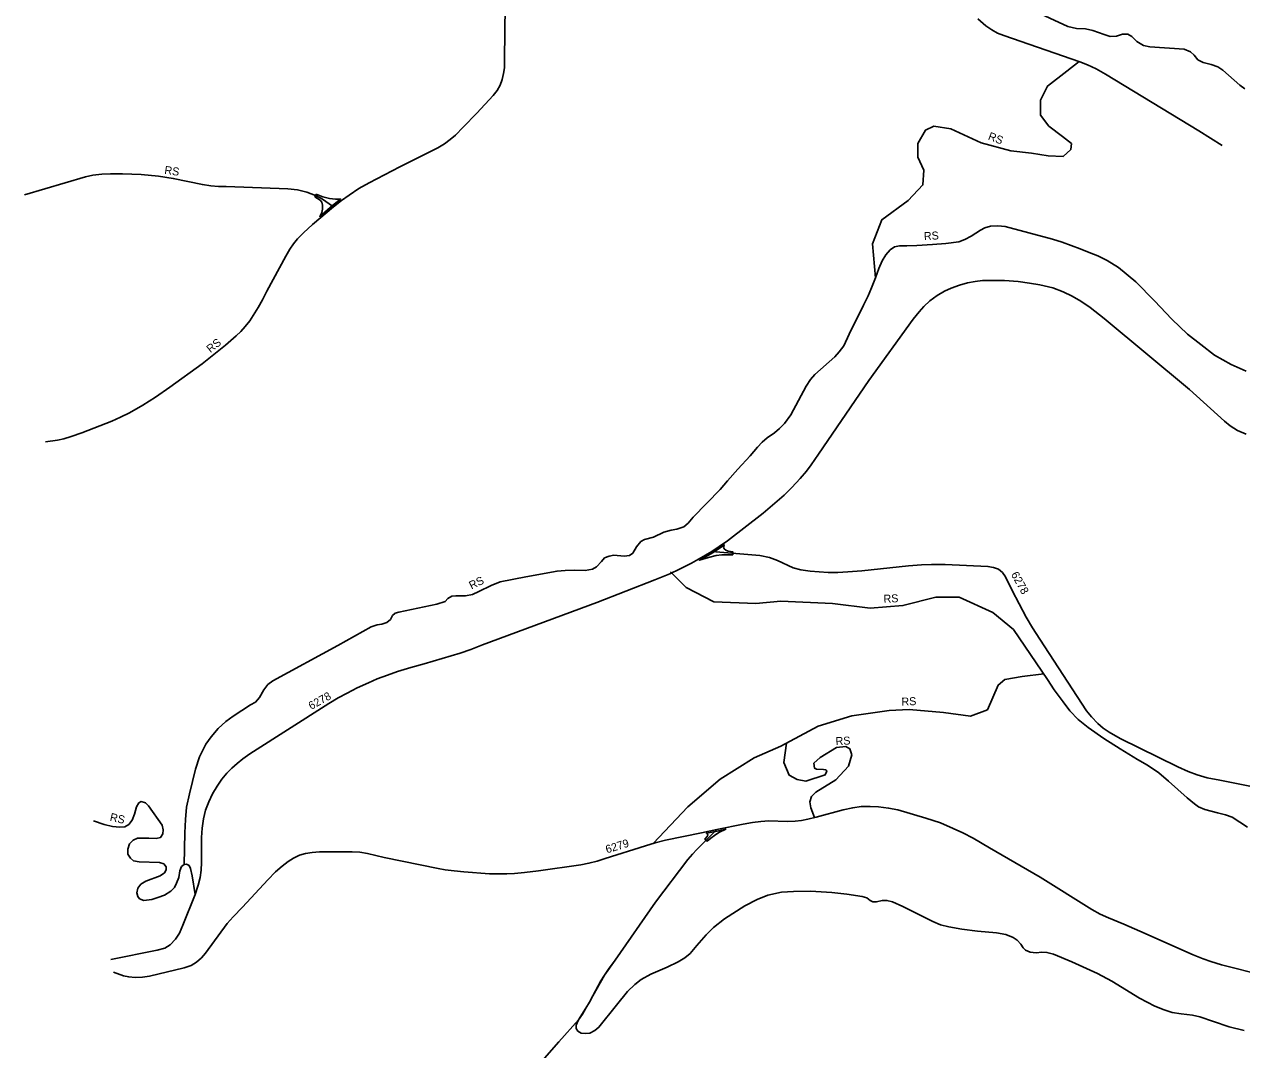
# Model space of a CAD drawing. Extents: x -546703 to -534152, y -1046534 to -1035676.
# Drawn here: x -546703 to -545182, y -1045782 to -1044501 of the extents above; entities that cross this region are included whole.
import ezdxf

# ---------------------------------------------------------------- set-up
doc = ezdxf.new("R2010")
doc.units = 0
doc.layers.add('Vrstva 11', color=7, linetype='Continuous')
doc.layers.add('Vrstva 22', color=7, linetype='Continuous')

msp = doc.modelspace()

# ---------------------------------------------------------------- linework, layer by layer
at = {"layer": 'Vrstva 11'}
for points in [[(-546676, -1045022.9), (-546661.2, -1045020.6), (-546653.1, -1045018.9), (-546644.2, -1045016.2), (-546630.9, -1045011.5), (-546593.5, -1044996.9), (-546582.7, -1044992), (-546571.2, -1044986.4), (-546554.5, -1044976.9), (-546538.8, -1044967), (-546521, -1044954.6), (-546480.4, -1044925.5), (-546451.3, -1044902.2), (-546437.8, -1044890.2), (-546432.3, -1044884.8), (-546426.6, -1044878.6), (-546421.1, -1044871.5), (-546416.6, -1044864.9), (-546410.4, -1044855), (-546405, -1044845.6), (-546399.5, -1044834.8), (-546376.1, -1044790.9), (-546371.1, -1044782.3), (-546366.5, -1044775.5), (-546361.4, -1044769.4), (-546353.7, -1044761.7), (-546342.4, -1044751.4), (-546316.5, -1044729.3), (-546306.3, -1044721.2), (-546296.8, -1044714.7), (-546284.5, -1044706.6), (-546271.9, -1044699.2), (-546233.4, -1044679.4), (-546185.9, -1044655.7), (-546177.7, -1044650.8), (-546170.5, -1044645.4), (-546163.9, -1044639.6), (-546154.4, -1044629.8), (-546137.3, -1044612.3), (-546116.7, -1044590.1), (-546111.8, -1044584.1), (-546108.3, -1044577.3), (-546105.8, -1044570.4), (-546103.8, -1044562.7), (-546102.9, -1044555.6), (-546102.5, -1044544.8), (-546102, -1044477.9)], [(-545511.3, -1044494.4), (-545501.1, -1044503.4), (-545493.9, -1044508.4), (-545486.9, -1044512.3), (-545478.9, -1044515.5), (-545383.7, -1044548.1), (-545374.1, -1044552), (-545363.5, -1044557), (-545351.7, -1044563.6), (-545235.3, -1044634.5), (-545206.2, -1044652.5)], [(-546702.6, -1044714.5), (-546626.2, -1044691.8), (-546617.2, -1044689.9), (-546605.7, -1044688.3), (-546594.8, -1044687.9), (-546580.2, -1044687.9), (-546556.6, -1044689.1), (-546535.1, -1044691), (-546516.5, -1044693.7), (-546480.1, -1044701.5), (-546469.8, -1044703), (-546460.1, -1044703.7), (-546450.5, -1044703.8), (-546373.6, -1044706.7), (-546361.4, -1044708.2), (-546349.8, -1044711), (-546338.8, -1044715), (-546331.4, -1044719), (-546316.5, -1044729.3)], [(-546594.6, -1045669.3), (-546536.5, -1045657.6), (-546527.2, -1045655), (-546520.4, -1045650.8), (-546513.9, -1045643.9), (-546508.9, -1045636.2), (-546504.6, -1045626.5), (-546489.1, -1045588.2), (-546485.5, -1045576.6), (-546483, -1045566.7), (-546481.8, -1045557.7), (-546481.2, -1045548), (-546481.2, -1045516.9), (-546480.4, -1045505.3), (-546478.6, -1045493.4), (-546476.2, -1045482.7), (-546472.3, -1045472.2), (-546467.5, -1045462.3), (-546461.8, -1045452.8), (-546455.8, -1045444), (-546449.7, -1045436.7), (-546443.5, -1045430.4), (-546436.8, -1045424.4), (-546429.7, -1045418.7), (-546420.9, -1045412.6), (-546322.2, -1045349.4), (-546310.5, -1045342.4), (-546299.4, -1045336.5), (-546286.8, -1045330), (-546272.5, -1045323.6), (-546261.8, -1045318.9), (-546248.7, -1045314.1), (-546236.4, -1045309.8), (-546219.8, -1045304.8), (-546202.9, -1045300), (-546158.1, -1045286.6), (-546144.9, -1045282), (-546130.2, -1045276.3), (-545987.5, -1045223.6), (-545915, -1045195.3), (-545896.3, -1045187.7), (-545884.2, -1045181.8), (-545869.2, -1045174.3), (-545851.7, -1045164.4), (-545843.6, -1045159.8), (-545834.3, -1045153.7), (-545824.2, -1045146.3), (-545779.4, -1045111.7), (-545767.7, -1045101.8), (-545753.2, -1045089.5), (-545743.7, -1045079.8), (-545733.4, -1045068.7), (-545725.5, -1045059.4), (-545719.5, -1045051.5), (-545710.2, -1045038), (-545647.6, -1044946.3), (-545591.9, -1044869.6), (-545584.4, -1044860.3), (-545578.7, -1044853.7), (-545571.1, -1044846.6), (-545562.1, -1044840), (-545552.8, -1044834.6), (-545544.6, -1044830.9), (-545534, -1044827), (-545524.4, -1044824.3), (-545514.8, -1044822.6), (-545505.4, -1044821.5), (-545495.2, -1044821.2), (-545478.1, -1044821.5), (-545460.9, -1044822.7), (-545446.9, -1044824.5), (-545434, -1044826.5), (-545417.6, -1044830.5), (-545404.6, -1044835.3), (-545393.3, -1044840.9), (-545382.4, -1044847.1), (-545371, -1044855), (-545353.6, -1044868.8), (-545246.9, -1044957.6), (-545203.1, -1044997), (-545195.8, -1045002.7), (-545186.7, -1045008.5), (-545176.2, -1045013)], [(-545843.6, -1045159.8), (-545783.8, -1045164.8), (-545771.6, -1045167.3), (-545761.6, -1045171), (-545742.1, -1045180), (-545732.6, -1045182.5), (-545720.6, -1045184.5), (-545698.3, -1045186.1), (-545686.2, -1045186), (-545673.9, -1045185.3), (-545656.1, -1045184), (-545598, -1045177.8), (-545581.5, -1045176.5), (-545569, -1045175.8), (-545552.3, -1045176.1), (-545498.6, -1045178.3), (-545491.6, -1045179.6), (-545485.3, -1045182), (-545480.4, -1045186), (-545476.9, -1045191.5), (-545468.4, -1045208.3), (-545450.9, -1045241.7), (-545443.1, -1045255.1), (-545433.9, -1045269.1), (-545375.4, -1045358.7), (-545369.4, -1045366.4), (-545361.5, -1045374.4), (-545354.7, -1045380.2), (-545347.2, -1045385.2), (-545333.5, -1045393.1), (-545261.4, -1045428.5), (-545248.3, -1045434.5), (-545237.3, -1045438.7), (-545224.7, -1045442.3), (-545208.9, -1045445.5), (-545136.2, -1045459.8)], [(-546591.2, -1045685), (-546578.9, -1045689.6), (-546572.1, -1045691.1), (-546564.3, -1045691.8), (-546555.1, -1045691.2), (-546546.1, -1045690), (-546503.1, -1045679.7), (-546494.3, -1045676.7), (-546487.4, -1045672.5), (-546481.2, -1045667), (-546476.2, -1045661.4), (-546449.1, -1045624.4), (-546441.8, -1045615.9), (-546430.2, -1045603.9), (-546398.3, -1045569.7), (-546388.7, -1045559.9), (-546380.6, -1045552.8), (-546373.2, -1045546.9), (-546366.3, -1045542.6), (-546358.9, -1045539), (-546351.2, -1045536.7), (-546343.1, -1045535.5), (-546333.7, -1045534.9), (-546292.9, -1045534.7), (-546283.5, -1045535.4), (-546273.7, -1045537.1), (-546252.9, -1045541.9), (-546185.7, -1045555.6), (-546177, -1045557.2), (-546165.6, -1045558.7), (-546153.7, -1045559.9), (-546121.4, -1045562.2), (-546109.7, -1045562.5), (-546099.8, -1045562.4), (-546090.1, -1045561.8), (-546077.8, -1045560.5), (-546060.1, -1045558.6), (-546007.5, -1045551.1), (-545997.3, -1045549.1), (-545987.1, -1045546.4), (-545977, -1045543.3), (-545926.5, -1045527.3), (-545914.5, -1045523.5), (-545901.5, -1045520.2), (-545856.7, -1045511.1), (-545837.4, -1045507.1), (-545804.7, -1045500.3), (-545793, -1045498.2), (-545782.5, -1045496.9), (-545772.6, -1045496.3), (-545749.4, -1045496.9), (-545739.6, -1045496.4), (-545731.6, -1045495.6), (-545723.7, -1045494.1), (-545713.3, -1045491.5), (-545679.7, -1045482.4), (-545667.6, -1045479.7), (-545657, -1045478.4), (-545646, -1045478.1), (-545635.2, -1045478.7), (-545622.8, -1045480.1), (-545611.4, -1045482.4), (-545576.1, -1045492.6), (-545558.1, -1045498.8), (-545542.1, -1045505.7), (-545530.2, -1045511), (-545517.2, -1045517.8), (-545496.8, -1045529.8), (-545433.6, -1045566.4), (-545368.9, -1045606.8), (-545358.3, -1045612.5), (-545348.1, -1045617.3), (-545328.8, -1045625.2), (-545309, -1045633.7), (-545242.2, -1045663.3), (-545229.7, -1045668.3), (-545220, -1045671.9), (-545206.8, -1045676), (-545101, -1045702.4)], [(-546070.6, -1045813), (-546034.9, -1045772.2), (-546010.4, -1045744.6), (-546005.4, -1045737.6), (-546000.9, -1045730.1), (-545996.5, -1045722.5), (-545992.4, -1045714.7), (-545982.2, -1045696.1), (-545977.7, -1045688.8), (-545972.1, -1045680.3), (-545964.4, -1045670), (-545914, -1045597.8), (-545873.6, -1045544.4), (-545867.9, -1045537.7), (-545862.5, -1045531.7), (-545837.4, -1045507.1)]]:
    msp.add_lwpolyline(points, dxfattribs=at)
for points in [[(-546338.1, -1044713.4), (-546329.6, -1044716.8), (-546321.3, -1044718.7), (-546314, -1044719.7), (-546307.5, -1044719.6), (-546317.8, -1044727.7), (-546333.5, -1044741.2), (-546331, -1044736.4), (-546330, -1044732.1), (-546330.1, -1044727.3), (-546331, -1044723.6), (-546333, -1044720.8), (-546339.5, -1044716.6)], [(-545833.3, -1045155.2), (-545842.7, -1045161.3), (-545850.8, -1045166), (-545859.1, -1045170.6), (-545847.8, -1045167.2), (-545838.3, -1045164.7), (-545831.1, -1045163.8), (-545817.5, -1045163.7), (-545817.4, -1045160.2), (-545823.4, -1045159.3), (-545826.3, -1045158.1), (-545828.3, -1045156.4), (-545828.9, -1045154.3), (-545828.1, -1045151.3)], [(-545837, -1045508.8), (-545826.3, -1045506.6), (-545834.7, -1045510.6), (-545840.5, -1045514.4), (-545844.8, -1045517.6), (-545849.5, -1045521.4), (-545852.2, -1045519.1), (-545849.4, -1045515.8), (-545848.7, -1045514), (-545849, -1045512.7), (-545850.5, -1045511.6)]]:
    msp.add_lwpolyline(points, close=True, dxfattribs=at)
at = {"layer": 'Vrstva 22'}
for points in [[(-545177.7, -1044581.8), (-545183.8, -1044577.3), (-545205.3, -1044558.7), (-545211.4, -1044554.5), (-545219.7, -1044551.7), (-545229.6, -1044549.1), (-545236.3, -1044545.6), (-545241.1, -1044539.8), (-545245.6, -1044535.6), (-545253.3, -1044532.4), (-545296.2, -1044529.5), (-545304.2, -1044527.6), (-545312.6, -1044522.8), (-545318.7, -1044516.7), (-545323.8, -1044513.8), (-545330.5, -1044513.5), (-545338.2, -1044516.1), (-545345.9, -1044516.4), (-545353.6, -1044514.2), (-545367.7, -1044509), (-545376.9, -1044507.1), (-545388.2, -1044506.5), (-545398.7, -1044504.2), (-545471.7, -1044469.9)], [(-545639.3, -1044818.1), (-545642.7, -1044775.3), (-545631.4, -1044745.5), (-545598.3, -1044721.3), (-545579.8, -1044701.9), (-545578.9, -1044683.4), (-545586.2, -1044667.2), (-545586.2, -1044650.3), (-545576.5, -1044633.4), (-545566.1, -1044628.5), (-545545.1, -1044631.7), (-545507.2, -1044649.5), (-545470.1, -1044659.2), (-545444.2, -1044662.4), (-545423.3, -1044665.6), (-545404.7, -1044666.4), (-545395, -1044657.6), (-545394.2, -1044650.3), (-545405.5, -1044641.4), (-545422.4, -1044628.5), (-545432.9, -1044614.8), (-545432.9, -1044596.2), (-545424.1, -1044578.5), (-545399.9, -1044560), (-545384.5, -1044547.8)], [(-546702.6, -1044714.5), (-546626.2, -1044691.8), (-546617.2, -1044689.9), (-546605.7, -1044688.3), (-546594.8, -1044687.9), (-546580.2, -1044687.9), (-546556.6, -1044689.1), (-546535.1, -1044691), (-546516.5, -1044693.7), (-546480.1, -1044701.5), (-546469.8, -1044703), (-546460.1, -1044703.7), (-546450.5, -1044703.8), (-546373.6, -1044706.7), (-546361.4, -1044708.2), (-546349.8, -1044711), (-546338.8, -1044715), (-546331.4, -1044719), (-546316.5, -1044729.3)], [(-546676, -1045022.9), (-546661.2, -1045020.6), (-546653.1, -1045018.9), (-546644.2, -1045016.2), (-546630.9, -1045011.5), (-546593.5, -1044996.9), (-546582.7, -1044992), (-546571.2, -1044986.4), (-546554.5, -1044976.9), (-546538.8, -1044967), (-546521, -1044954.6), (-546480.4, -1044925.5), (-546451.3, -1044902.2), (-546437.8, -1044890.2), (-546432.3, -1044884.8), (-546426.6, -1044878.6), (-546421.1, -1044871.5), (-546416.6, -1044864.9), (-546410.4, -1044855), (-546405, -1044845.6), (-546399.5, -1044834.8), (-546376.1, -1044790.9), (-546371.1, -1044782.3), (-546366.5, -1044775.5), (-546361.4, -1044769.4), (-546353.7, -1044761.7), (-546342.4, -1044751.4), (-546316.5, -1044729.3)], [(-546503, -1045550.6), (-546502, -1045511), (-546501.3, -1045494.3), (-546499.9, -1045478.9), (-546496.4, -1045462.4), (-546488.6, -1045431.6), (-546483.7, -1045416), (-546475.9, -1045400.5), (-546469.3, -1045391), (-546460.4, -1045380.9), (-546450.7, -1045371.9), (-546441.8, -1045365.3), (-546420.1, -1045351.4), (-546413.7, -1045347.9), (-546408.8, -1045342), (-546403.6, -1045332.4), (-546398.2, -1045325.8), (-546392.1, -1045321.3), (-546311, -1045277.2), (-546269.1, -1045253.9), (-546261.6, -1045251.3), (-546256.1, -1045250.3), (-546249.8, -1045248.4), (-546245.3, -1045244.7), (-546242.7, -1045239.7), (-546239.2, -1045236.9), (-546234.9, -1045235.7), (-546187.1, -1045225.4), (-546177, -1045222.1), (-546173.5, -1045218.5), (-546168.5, -1045215.5), (-546163.3, -1045215), (-546151.3, -1045215), (-546142.6, -1045213.3), (-546134.8, -1045209.6), (-546119.5, -1045202), (-546108, -1045197.8), (-546076.2, -1045191.4), (-546036.9, -1045184.1), (-546026.7, -1045183.4), (-546015.7, -1045183.2), (-546002, -1045183.6), (-545992.8, -1045181.7), (-545987.6, -1045178.7), (-545981.7, -1045172.3), (-545977.7, -1045167.6), (-545972.1, -1045165.5), (-545966, -1045164.5), (-545953.2, -1045165.7), (-545946.6, -1045164.8), (-545942.4, -1045161.7), (-545937.7, -1045153.9), (-545932.3, -1045147.1), (-545927.8, -1045144.7), (-545916.5, -1045141.9), (-545903.5, -1045135.8), (-545894.6, -1045133.2), (-545887.3, -1045132), (-545878.6, -1045129), (-545873.4, -1045124.2), (-545866.8, -1045116.9), (-545833.1, -1045082.3), (-545823.9, -1045071.4), (-545811, -1045057.1), (-545795.9, -1045040.3), (-545786.5, -1045029.5), (-545780.8, -1045023.4), (-545774.5, -1045017.7), (-545765.5, -1045011.6), (-545759.2, -1045006.2), (-545752.8, -1045000), (-545745, -1044989), (-545725.7, -1044953.4), (-545720.3, -1044945.1), (-545714.9, -1044938.8), (-545689.9, -1044916.6), (-545684.5, -1044910.5), (-545678.8, -1044902.9), (-545672.2, -1044888.3), (-545654.3, -1044852), (-545648.2, -1044840.5), (-545644.2, -1044830.3), (-545639.3, -1044818.1), (-545635, -1044806.3), (-545631, -1044796.9), (-545626.3, -1044789.3), (-545620.9, -1044783.2), (-545615.2, -1044779.4), (-545609.3, -1044778), (-545599.9, -1044777.8), (-545587.7, -1044777.6), (-545568.1, -1044776.4), (-545551.2, -1044775.2), (-545535.2, -1044772.8), (-545527.4, -1044770.2), (-545519.8, -1044766), (-545508.1, -1044758.5), (-545502.6, -1044755.6), (-545495.3, -1044753.5), (-545486.4, -1044753), (-545477, -1044754), (-545418.1, -1044769.5), (-545405.8, -1044773.5), (-545383.5, -1044781.8), (-545372.2, -1044786.3), (-545361.3, -1044790.5), (-545349.7, -1044796.5), (-545335.6, -1044805.1), (-545313.9, -1044823.1), (-545290.5, -1044846.5), (-545268.7, -1044869.6), (-545249.2, -1044888.5), (-545232.5, -1044901.3), (-545215.5, -1044914.7), (-545194.7, -1044926), (-545176.1, -1044934.6)], [(-546594.6, -1045669.3), (-546536.5, -1045657.6), (-546527.2, -1045655), (-546520.4, -1045650.8), (-546513.9, -1045643.9), (-546508.9, -1045636.2), (-546504.6, -1045626.5), (-546489.1, -1045588.2), (-546485.5, -1045576.6), (-546483, -1045566.7), (-546481.8, -1045557.7), (-546481.2, -1045548), (-546481.2, -1045516.9), (-546480.4, -1045505.3), (-546478.6, -1045493.4), (-546476.2, -1045482.7), (-546472.3, -1045472.2), (-546467.5, -1045462.3), (-546461.8, -1045452.8), (-546455.8, -1045444), (-546449.7, -1045436.7), (-546443.5, -1045430.4), (-546436.8, -1045424.4), (-546429.7, -1045418.7), (-546420.9, -1045412.6), (-546322.2, -1045349.4), (-546310.5, -1045342.4), (-546299.4, -1045336.5), (-546286.8, -1045330), (-546272.5, -1045323.6), (-546261.8, -1045318.9), (-546248.7, -1045314.1), (-546236.4, -1045309.8), (-546219.8, -1045304.8), (-546202.9, -1045300), (-546158.1, -1045286.6), (-546144.9, -1045282), (-546130.2, -1045276.3), (-545987.5, -1045223.6), (-545915, -1045195.3), (-545896.3, -1045187.7), (-545884.2, -1045181.8), (-545869.2, -1045174.3), (-545851.7, -1045164.4), (-545843.6, -1045159.8)], [(-545843.6, -1045159.8), (-545783.8, -1045164.8), (-545771.6, -1045167.3), (-545761.6, -1045171), (-545742.1, -1045180), (-545732.6, -1045182.5), (-545720.6, -1045184.5), (-545698.3, -1045186.1), (-545686.2, -1045186), (-545673.9, -1045185.3), (-545656.1, -1045184), (-545598, -1045177.8), (-545581.5, -1045176.5), (-545569, -1045175.8), (-545552.3, -1045176.1), (-545498.6, -1045178.3), (-545491.6, -1045179.6), (-545485.3, -1045182), (-545480.4, -1045186), (-545476.9, -1045191.5), (-545468.4, -1045208.3), (-545450.9, -1045241.7), (-545443.1, -1045255.1), (-545433.9, -1045269.1), (-545375.4, -1045358.7), (-545369.4, -1045366.4), (-545361.5, -1045374.4), (-545354.7, -1045380.2), (-545347.2, -1045385.2), (-545333.5, -1045393.1), (-545261.4, -1045428.5), (-545248.3, -1045434.5), (-545237.3, -1045438.7), (-545224.7, -1045442.3), (-545208.9, -1045445.5), (-545136.2, -1045459.8)], [(-545424.2, -1045319.6), (-545466.9, -1045257.1), (-545492.7, -1045236.1), (-545534.6, -1045216.8), (-545563.7, -1045216.8), (-545604.8, -1045227.2), (-545646, -1045230.5), (-545692.8, -1045224.8), (-545757.3, -1045221.6), (-545788.8, -1045224.8), (-545841.2, -1045222.4), (-545875.9, -1045204.7), (-545895.2, -1045185.3)], [(-545917, -1045524.3), (-545873.7, -1045478.7), (-545833.3, -1045444.1), (-545790.6, -1045417.4), (-545757.5, -1045402.9), (-545710.7, -1045377.9), (-545668.8, -1045365), (-545622, -1045358.5), (-545596.9, -1045356.9), (-545554.2, -1045361), (-545520.3, -1045365.2), (-545499.3, -1045357.6), (-545486, -1045326.5), (-545477.6, -1045319.8), (-545455.8, -1045315.8), (-545429, -1045312.6)], [(-545174.5, -1045504.2), (-545184, -1045497.6), (-545193.4, -1045491.7), (-545201.9, -1045488.8), (-545212, -1045486.3), (-545227.8, -1045482), (-545235.5, -1045478.5), (-545240.5, -1045474.9), (-545249.7, -1045467.4), (-545273, -1045446.7), (-545285.2, -1045436.1), (-545299.4, -1045426.4), (-545311.6, -1045419.3), (-545333.5, -1045406.1), (-545353.8, -1045393.2), (-545373.3, -1045379.7), (-545386.1, -1045369.4), (-545396.2, -1045358.7), (-545404.7, -1045347.4), (-545416, -1045332.6), (-545424.2, -1045319.6)], [(-545715.5, -1045492.1), (-545720, -1045480), (-545721.2, -1045472.3), (-545719.2, -1045465.8), (-545713.9, -1045460.2), (-545688.9, -1045444.9), (-545672.8, -1045427.9), (-545668.7, -1045413.5), (-545671.2, -1045406.1), (-545676.3, -1045403.4), (-545687.9, -1045404.7), (-545708.1, -1045417.2), (-545716, -1045424), (-545715.5, -1045430.2), (-545712.8, -1045431.4), (-545704.3, -1045432.1), (-545701.4, -1045432.5), (-545700.1, -1045434.1), (-545702, -1045438.6), (-545726, -1045446.5), (-545737, -1045444.6), (-545747, -1045439.2), (-545753.5, -1045423.1), (-545750.4, -1045399.1)], [(-546616.1, -1045496.2), (-546602.9, -1045500.6), (-546592.3, -1045503), (-546583.3, -1045504.2), (-546577.2, -1045503.5), (-546572, -1045500.6), (-546568, -1045495.4), (-546564.9, -1045487.7), (-546562.3, -1045478.5), (-546559.5, -1045473.8), (-546556.5, -1045472.1), (-546551.3, -1045473.8), (-546547.3, -1045477.3), (-546530.5, -1045501.6), (-546529.1, -1045507.2), (-546529.6, -1045512.4), (-546532.4, -1045516.9), (-546538.1, -1045518.3), (-546547, -1045517.8), (-546553.4, -1045517.6), (-546561.4, -1045517.8), (-546566.8, -1045520.2), (-546571.1, -1045524.7), (-546573.2, -1045531.5), (-546573.2, -1045537.6), (-546570.1, -1045542.6), (-546566.1, -1045545.9), (-546559.1, -1045547.1), (-546533.6, -1045548), (-546528.4, -1045549.9), (-546525.6, -1045553.4), (-546525.6, -1045557.4), (-546527.5, -1045561), (-546533.1, -1045564.7), (-546551, -1045571.6), (-546556.9, -1045575.1), (-546560.7, -1045580.1), (-546562.1, -1045586.2), (-546560.9, -1045590.7), (-546558.6, -1045593.7), (-546553.4, -1045595.4), (-546543.3, -1045594.4), (-546535.7, -1045591.8), (-546527.5, -1045588.8), (-546519.7, -1045584.1), (-546515.2, -1045579.3), (-546512.4, -1045573.9), (-546509.8, -1045566.9), (-546508.2, -1045558.4), (-546506.3, -1045553.2), (-546503, -1045550.6), (-546499.9, -1045550.1), (-546496.9, -1045551.8), (-546495, -1045555.8), (-546493.1, -1045564.7), (-546489.1, -1045588.2)], [(-545837.4, -1045507.1), (-545804.7, -1045500.3), (-545793, -1045498.2), (-545782.5, -1045496.9), (-545772.6, -1045496.3), (-545749.4, -1045496.9), (-545739.6, -1045496.4), (-545731.6, -1045495.6), (-545723.7, -1045494.1), (-545713.3, -1045491.5), (-545679.7, -1045482.4), (-545667.6, -1045479.7), (-545657, -1045478.4), (-545646, -1045478.1), (-545635.2, -1045478.7), (-545622.8, -1045480.1), (-545611.4, -1045482.4), (-545576.1, -1045492.6), (-545558.1, -1045498.8), (-545542.1, -1045505.7), (-545530.2, -1045511), (-545517.2, -1045517.8), (-545496.8, -1045529.8), (-545433.6, -1045566.4), (-545368.9, -1045606.8), (-545358.3, -1045612.5), (-545348.1, -1045617.3), (-545328.8, -1045625.2), (-545309, -1045633.7), (-545242.2, -1045663.3), (-545229.7, -1045668.3), (-545220, -1045671.9), (-545206.8, -1045676), (-545101, -1045702.4)], [(-546591.2, -1045685), (-546578.9, -1045689.6), (-546572.1, -1045691.1), (-546564.3, -1045691.8), (-546555.1, -1045691.2), (-546546.1, -1045690), (-546503.1, -1045679.7), (-546494.3, -1045676.7), (-546487.4, -1045672.5), (-546481.2, -1045667), (-546476.2, -1045661.4), (-546449.1, -1045624.4), (-546441.8, -1045615.9), (-546430.2, -1045603.9), (-546398.3, -1045569.7), (-546388.7, -1045559.9), (-546380.6, -1045552.8), (-546373.2, -1045546.9), (-546366.3, -1045542.6), (-546358.9, -1045539), (-546351.2, -1045536.7), (-546343.1, -1045535.5), (-546333.7, -1045534.9), (-546292.9, -1045534.7), (-546283.5, -1045535.4), (-546273.7, -1045537.1), (-546252.9, -1045541.9), (-546185.7, -1045555.6), (-546177, -1045557.2), (-546165.6, -1045558.7), (-546153.7, -1045559.9), (-546121.4, -1045562.2), (-546109.7, -1045562.5), (-546099.8, -1045562.4), (-546090.1, -1045561.8), (-546077.8, -1045560.5), (-546060.1, -1045558.6), (-546007.5, -1045551.1), (-545997.3, -1045549.1), (-545987.1, -1045546.4), (-545977, -1045543.3), (-545926.5, -1045527.3), (-545914.5, -1045523.5), (-545901.5, -1045520.2), (-545856.7, -1045511.1), (-545837.4, -1045507.1)], [(-545837.4, -1045507.1), (-545862.5, -1045531.7), (-545867.9, -1045537.7), (-545873.6, -1045544.4), (-545914, -1045597.8), (-545964.4, -1045670), (-545977.7, -1045688.8), (-545992.4, -1045714.7), (-545992.4, -1045714.7), (-545996.5, -1045722.5), (-546000.9, -1045730.1), (-546010.4, -1045744.6), (-546013.3, -1045751.4), (-546013.3, -1045755.4), (-546011.2, -1045758.7), (-546006.7, -1045761.3), (-546001.5, -1045761.5), (-545995.9, -1045761.1), (-545989.7, -1045758), (-545984.8, -1045753.8), (-545962.9, -1045726.2), (-545949, -1045709.4), (-545940, -1045700.5), (-545932, -1045694.4), (-545919.8, -1045687.5), (-545899.3, -1045679), (-545885.6, -1045672.4), (-545877.4, -1045667.3), (-545870.8, -1045661.6), (-545862.3, -1045651.7), (-545850.8, -1045638.3), (-545841.4, -1045629.3), (-545827.7, -1045618.7), (-545802.3, -1045602.4), (-545786.9, -1045594.2), (-545773.8, -1045588.8), (-545756.8, -1045585.2), (-545741.7, -1045584.3), (-545720.3, -1045583.8), (-545693.7, -1045585.5), (-545674.8, -1045587.8), (-545656, -1045590.4), (-545650.1, -1045592.3), (-545645.9, -1045595.6), (-545642.3, -1045597.3), (-545638.3, -1045597.3), (-545630.5, -1045595.4), (-545624.9, -1045595.4), (-545617.8, -1045597.3), (-545605.1, -1045603.2), (-545567.4, -1045622), (-545558, -1045625.8), (-545547.4, -1045628.4), (-545531.1, -1045631.4), (-545511.6, -1045634), (-545488, -1045636.1), (-545476.5, -1045638), (-545467.1, -1045642), (-545462.1, -1045645.3), (-545457.7, -1045650.3), (-545454.6, -1045654.8), (-545451.8, -1045657.8), (-545445.9, -1045660.2), (-545438.3, -1045661.1), (-545431.3, -1045660), (-545424.9, -1045660.4), (-545416.9, -1045662.8), (-545393.8, -1045672.2), (-545361.8, -1045686.8), (-545343.7, -1045696.5), (-545309.3, -1045717.5), (-545290.2, -1045727.6), (-545278.4, -1045732.3), (-545268.3, -1045735.6), (-545257.2, -1045737), (-545243.1, -1045738.7), (-545234.1, -1045740.8), (-545216.9, -1045746.7), (-545197.4, -1045753.5), (-545178.5, -1045758)]]:
    msp.add_lwpolyline(points, dxfattribs=at)

# ---------------------------------------------------------------- texts
for s, rotation, p in [('RS', 339.4106, (-545499.3, -1044645)), ('RS', 351.922, (-546528.1, -1044688)), ('RS', 3.4495, (-545578.4, -1044771)), ('RS', 38.7082, (-546470.1, -1044912.1)), ('6278', 299.1297, (-545470.2, -1045188.3)), ('RS', 25.88, (-546144, -1045207.3)), ('RS', 2.7828, (-545628.9, -1045223.9)), ('6278', 29.1297, (-546344.2, -1045357.7)), ('RS', 2.7828, (-545606.5, -1045352.4)), ('RS', 2.7828, (-545688.8, -1045401.6)), ('RS', 347.4638, (-546596.4, -1045495.9)), ('6279', 17.0179, (-545974.7, -1045536.8))]:
    msp.add_text(s, height=10, rotation=rotation, dxfattribs=at).set_placement(p)

doc.saveas('drawing.dxf')
